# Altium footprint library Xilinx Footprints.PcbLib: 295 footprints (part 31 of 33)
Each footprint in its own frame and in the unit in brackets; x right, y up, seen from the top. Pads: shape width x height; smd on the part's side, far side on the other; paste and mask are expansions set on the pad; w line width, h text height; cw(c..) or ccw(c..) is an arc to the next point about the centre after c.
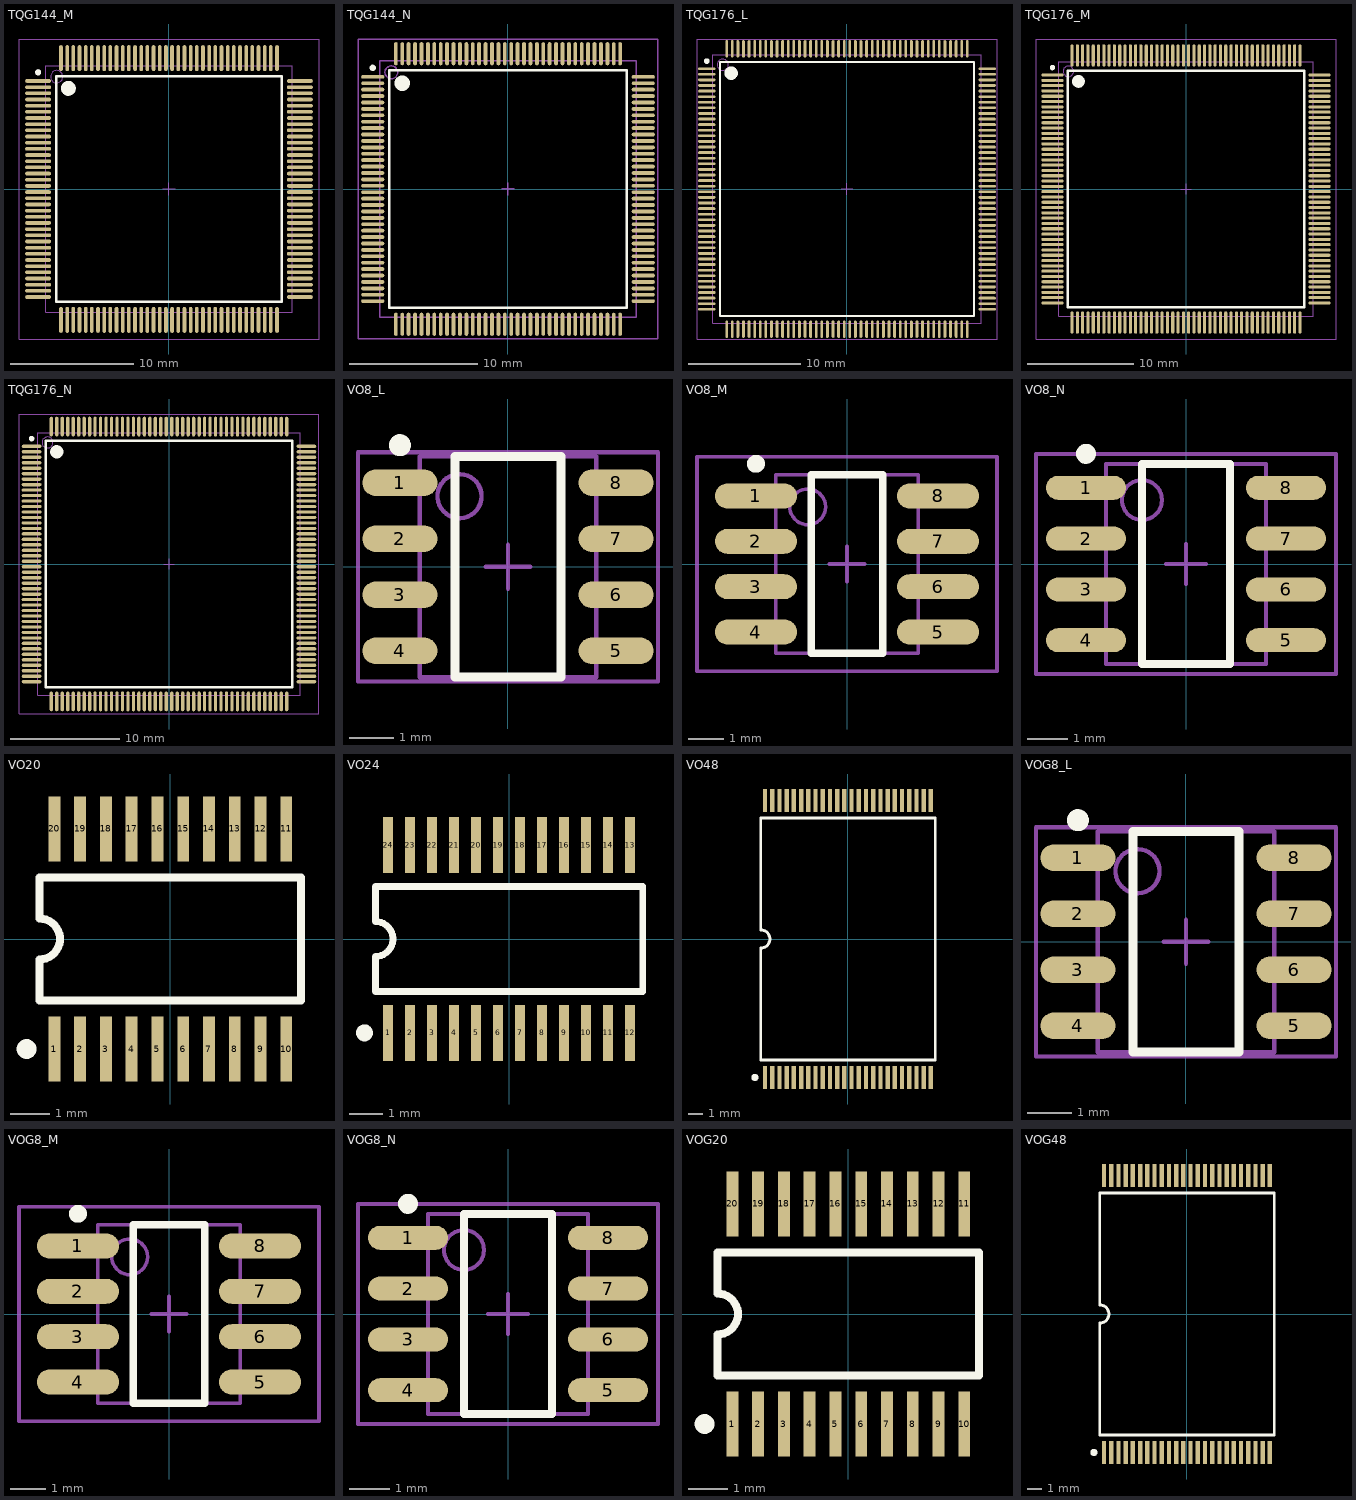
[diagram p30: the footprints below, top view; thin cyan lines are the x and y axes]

## TQG144_M [mm] "144-Pin Thin Quad Flat Pack (TQG144) - Pb-Free, IPC Low Density"
height 1.6
pads (144):
  oval 2.1x0.3 smd: 1(-10.6,8.75) 2(-10.6,8.25) 3(-10.6,7.75) 4(-10.6,7.25) 5(-10.6,6.75) 6(-10.6,6.25) 7(-10.6,5.75) 8(-10.6,5.25) 9(-10.6,4.75) 10(-10.6,4.25) 11(-10.6,3.75) 12(-10.6,3.25) 13(-10.6,2.75) 14(-10.6,2.25) 15(-10.6,1.75) 16(-10.6,1.25) 17(-10.6,0.75) 18(-10.6,0.25) 19(-10.6,-0.25) 20(-10.6,-0.75) 21(-10.6,-1.25) 22(-10.6,-1.75) 23(-10.6,-2.25) 24(-10.6,-2.75) 25(-10.6,-3.25) 26(-10.6,-3.75) 27(-10.6,-4.25) 28(-10.6,-4.75) 29(-10.6,-5.25) 30(-10.6,-5.75) 31(-10.6,-6.25) 32(-10.6,-6.75) 33(-10.6,-7.25) 34(-10.6,-7.75) 35(-10.6,-8.25) 36(-10.6,-8.75) 73(10.6,-8.75) 74(10.6,-8.25) 75(10.6,-7.75) 76(10.6,-7.25) 77(10.6,-6.75) 78(10.6,-6.25) 79(10.6,-5.75) 80(10.6,-5.25) 81(10.6,-4.75) 82(10.6,-4.25) 83(10.6,-3.75) 84(10.6,-3.25) 85(10.6,-2.75) 86(10.6,-2.25) 87(10.6,-1.75) 88(10.6,-1.25) 89(10.6,-0.75) 90(10.6,-0.25) 91(10.6,0.25) 92(10.6,0.75) 93(10.6,1.25) 94(10.6,1.75) 95(10.6,2.25) 96(10.6,2.75) 97(10.6,3.25) 98(10.6,3.75) 99(10.6,4.25) 100(10.6,4.75) 101(10.6,5.25) 102(10.6,5.75) 103(10.6,6.25) 104(10.6,6.75) 105(10.6,7.25) 106(10.6,7.75) 107(10.6,8.25) 108(10.6,8.75)
  oval 0.3x2.1 smd: 37(-8.75,-10.6) 38(-8.25,-10.6) 39(-7.75,-10.6) 40(-7.25,-10.6) 41(-6.75,-10.6) 42(-6.25,-10.6) 43(-5.75,-10.6) 44(-5.25,-10.6) 45(-4.75,-10.6) 46(-4.25,-10.6) 47(-3.75,-10.6) 48(-3.25,-10.6) 49(-2.75,-10.6) 50(-2.25,-10.6) 51(-1.75,-10.6) 52(-1.25,-10.6) 53(-0.75,-10.6) 54(-0.25,-10.6) 55(0.25,-10.6) 56(0.75,-10.6) 57(1.25,-10.6) 58(1.75,-10.6) 59(2.25,-10.6) 60(2.75,-10.6) 61(3.25,-10.6) 62(3.75,-10.6) 63(4.25,-10.6) 64(4.75,-10.6) 65(5.25,-10.6) 66(5.75,-10.6) 67(6.25,-10.6) 68(6.75,-10.6) 69(7.25,-10.6) 70(7.75,-10.6) 71(8.25,-10.6) 72(8.75,-10.6) 109(8.75,10.6) 110(8.25,10.6) 111(7.75,10.6) 112(7.25,10.6) 113(6.75,10.6) 114(6.25,10.6) 115(5.75,10.6) 116(5.25,10.6) 117(4.75,10.6) 118(4.25,10.6) 119(3.75,10.6) 120(3.25,10.6) 121(2.75,10.6) 122(2.25,10.6) 123(1.75,10.6) 124(1.25,10.6) 125(0.75,10.6) 126(0.25,10.6) 127(-0.25,10.6) 128(-0.75,10.6) 129(-1.25,10.6) 130(-1.75,10.6) 131(-2.25,10.6) 132(-2.75,10.6) 133(-3.25,10.6) 134(-3.75,10.6) 135(-4.25,10.6) 136(-4.75,10.6) 137(-5.25,10.6) 138(-5.75,10.6) 139(-6.25,10.6) 140(-6.75,10.6) 141(-7.25,10.6) 142(-7.75,10.6) 143(-8.25,10.6) 144(-8.75,10.6)
Top Overlay:
  circle w0.6: c-8.15,8.15 r0.3
  circle w0.25: c-10.6,9.45 r0.125
  lines w0.2: -9.15,-9.15 9.15,-9.15 9.15,9.15 -9.15,9.15 -9.15,-9.15
Mechanical 13:
  circle w0.1: c-9.1,9.1 r0.5
  lines w0.1: -10,-10 10,-10 10,10 -10,10 -10,-10
Mechanical 15:
  lines w0.1: -0.5,0 0.5,0 ; 0,-0.5 0,0.5 ; -12.15,-12.15 12.15,-12.15 12.15,12.15 -12.15,12.15 -12.15,-12.15
3D body: height 1.6, standoff 0, extent -10,-10 10,10

## TQG144_N [mm] "144-Pin Thin Quad Flat Pack (TQG144) - Pb-Free, IPC Medium Density"
height 1.6
pads (144):
  oval 1.8x0.3 smd: 1(-10.55,8.75) 2(-10.55,8.25) 3(-10.55,7.75) 4(-10.55,7.25) 5(-10.55,6.75) 6(-10.55,6.25) 7(-10.55,5.75) 8(-10.55,5.25) 9(-10.55,4.75) 10(-10.55,4.25) 11(-10.55,3.75) 12(-10.55,3.25) 13(-10.55,2.75) 14(-10.55,2.25) 15(-10.55,1.75) 16(-10.55,1.25) 17(-10.55,0.75) 18(-10.55,0.25) 19(-10.55,-0.25) 20(-10.55,-0.75) 21(-10.55,-1.25) 22(-10.55,-1.75) 23(-10.55,-2.25) 24(-10.55,-2.75) 25(-10.55,-3.25) 26(-10.55,-3.75) 27(-10.55,-4.25) 28(-10.55,-4.75) 29(-10.55,-5.25) 30(-10.55,-5.75) 31(-10.55,-6.25) 32(-10.55,-6.75) 33(-10.55,-7.25) 34(-10.55,-7.75) 35(-10.55,-8.25) 36(-10.55,-8.75) 73(10.55,-8.75) 74(10.55,-8.25) 75(10.55,-7.75) 76(10.55,-7.25) 77(10.55,-6.75) 78(10.55,-6.25) 79(10.55,-5.75) 80(10.55,-5.25) 81(10.55,-4.75) 82(10.55,-4.25) 83(10.55,-3.75) 84(10.55,-3.25) 85(10.55,-2.75) 86(10.55,-2.25) 87(10.55,-1.75) 88(10.55,-1.25) 89(10.55,-0.75) 90(10.55,-0.25) 91(10.55,0.25) 92(10.55,0.75) 93(10.55,1.25) 94(10.55,1.75) 95(10.55,2.25) 96(10.55,2.75) 97(10.55,3.25) 98(10.55,3.75) 99(10.55,4.25) 100(10.55,4.75) 101(10.55,5.25) 102(10.55,5.75) 103(10.55,6.25) 104(10.55,6.75) 105(10.55,7.25) 106(10.55,7.75) 107(10.55,8.25) 108(10.55,8.75)
  oval 0.3x1.8 smd: 37(-8.75,-10.55) 38(-8.25,-10.55) 39(-7.75,-10.55) 40(-7.25,-10.55) 41(-6.75,-10.55) 42(-6.25,-10.55) 43(-5.75,-10.55) 44(-5.25,-10.55) 45(-4.75,-10.55) 46(-4.25,-10.55) 47(-3.75,-10.55) 48(-3.25,-10.55) 49(-2.75,-10.55) 50(-2.25,-10.55) 51(-1.75,-10.55) 52(-1.25,-10.55) 53(-0.75,-10.55) 54(-0.25,-10.55) 55(0.25,-10.55) 56(0.75,-10.55) 57(1.25,-10.55) 58(1.75,-10.55) 59(2.25,-10.55) 60(2.75,-10.55) 61(3.25,-10.55) 62(3.75,-10.55) 63(4.25,-10.55) 64(4.75,-10.55) 65(5.25,-10.55) 66(5.75,-10.55) 67(6.25,-10.55) 68(6.75,-10.55) 69(7.25,-10.55) 70(7.75,-10.55) 71(8.25,-10.55) 72(8.75,-10.55) 109(8.75,10.55) 110(8.25,10.55) 111(7.75,10.55) 112(7.25,10.55) 113(6.75,10.55) 114(6.25,10.55) 115(5.75,10.55) 116(5.25,10.55) 117(4.75,10.55) 118(4.25,10.55) 119(3.75,10.55) 120(3.25,10.55) 121(2.75,10.55) 122(2.25,10.55) 123(1.75,10.55) 124(1.25,10.55) 125(0.75,10.55) 126(0.25,10.55) 127(-0.25,10.55) 128(-0.75,10.55) 129(-1.25,10.55) 130(-1.75,10.55) 131(-2.25,10.55) 132(-2.75,10.55) 133(-3.25,10.55) 134(-3.75,10.55) 135(-4.25,10.55) 136(-4.75,10.55) 137(-5.25,10.55) 138(-5.75,10.55) 139(-6.25,10.55) 140(-6.75,10.55) 141(-7.25,10.55) 142(-7.75,10.55) 143(-8.25,10.55) 144(-8.75,10.55)
Top Overlay:
  circle w0.25: c-10.55,9.45 r0.125
  circle w0.6: c-8.25,8.25 r0.3
  lines w0.2: -9.25,-9.25 -9.25,9.25 9.25,9.25 9.25,-9.25 -9.25,-9.25
Mechanical 13:
  circle w0.1: c-9.1,9.1 r0.5
  lines w0.1: -10,-10 -10,10 10,10 10,-10 -10,-10
Mechanical 15:
  lines w0.1: -0.5,0 0.5,0 ; 0,-0.5 0,0.5 ; -11.7,-11.7 -11.7,11.7 11.7,11.7 11.7,-11.7 -11.7,-11.7
3D body: height 1.6, standoff 0, extent -10,-10 10,10

## TQG176_L [mm] "176-Pin Thin Quad Flat Pack (TQG176) - Pb-Free, IPC High Density"
height 1.6
pads (176):
  oval 1.55x0.25 smd: 1(-12.525,10.75) 2(-12.525,10.25) 3(-12.525,9.75) 4(-12.525,9.25) 5(-12.525,8.75) 6(-12.525,8.25) 7(-12.525,7.75) 8(-12.525,7.25) 9(-12.525,6.75) 10(-12.525,6.25) 11(-12.525,5.75) 12(-12.525,5.25) 13(-12.525,4.75) 14(-12.525,4.25) 15(-12.525,3.75) 16(-12.525,3.25) 17(-12.525,2.75) 18(-12.525,2.25) 19(-12.525,1.75) 20(-12.525,1.25) 21(-12.525,0.75) 22(-12.525,0.25) 23(-12.525,-0.25) 24(-12.525,-0.75) 25(-12.525,-1.25) 26(-12.525,-1.75) 27(-12.525,-2.25) 28(-12.525,-2.75) 29(-12.525,-3.25) 30(-12.525,-3.75) 31(-12.525,-4.25) 32(-12.525,-4.75) 33(-12.525,-5.25) 34(-12.525,-5.75) 35(-12.525,-6.25) 36(-12.525,-6.75) 37(-12.525,-7.25) 38(-12.525,-7.75) 39(-12.525,-8.25) 40(-12.525,-8.75) 41(-12.525,-9.25) 42(-12.525,-9.75) 43(-12.525,-10.25) 44(-12.525,-10.75) 89(12.525,-10.75) 90(12.525,-10.25) 91(12.525,-9.75) 92(12.525,-9.25) 93(12.525,-8.75) 94(12.525,-8.25) 95(12.525,-7.75) 96(12.525,-7.25) 97(12.525,-6.75) 98(12.525,-6.25) 99(12.525,-5.75) 100(12.525,-5.25) 101(12.525,-4.75) 102(12.525,-4.25) 103(12.525,-3.75) 104(12.525,-3.25) 105(12.525,-2.75) 106(12.525,-2.25) 107(12.525,-1.75) 108(12.525,-1.25) 109(12.525,-0.75) 110(12.525,-0.25) 111(12.525,0.25) 112(12.525,0.75) 113(12.525,1.25) 114(12.525,1.75) 115(12.525,2.25) 116(12.525,2.75) 117(12.525,3.25) 118(12.525,3.75) 119(12.525,4.25) 120(12.525,4.75) 121(12.525,5.25) 122(12.525,5.75) 123(12.525,6.25) 124(12.525,6.75) 125(12.525,7.25) 126(12.525,7.75) 127(12.525,8.25) 128(12.525,8.75) 129(12.525,9.25) 130(12.525,9.75) 131(12.525,10.25) 132(12.525,10.75)
  oval 0.25x1.55 smd: 45(-10.75,-12.525) 46(-10.25,-12.525) 47(-9.75,-12.525) 48(-9.25,-12.525) 49(-8.75,-12.525) 50(-8.25,-12.525) 51(-7.75,-12.525) 52(-7.25,-12.525) 53(-6.75,-12.525) 54(-6.25,-12.525) 55(-5.75,-12.525) 56(-5.25,-12.525) 57(-4.75,-12.525) 58(-4.25,-12.525) 59(-3.75,-12.525) 60(-3.25,-12.525) 61(-2.75,-12.525) 62(-2.25,-12.525) 63(-1.75,-12.525) 64(-1.25,-12.525) 65(-0.75,-12.525) 66(-0.25,-12.525) 67(0.25,-12.525) 68(0.75,-12.525) 69(1.25,-12.525) 70(1.75,-12.525) 71(2.25,-12.525) 72(2.75,-12.525) 73(3.25,-12.525) 74(3.75,-12.525) 75(4.25,-12.525) 76(4.75,-12.525) 77(5.25,-12.525) 78(5.75,-12.525) 79(6.25,-12.525) 80(6.75,-12.525) 81(7.25,-12.525) 82(7.75,-12.525) 83(8.25,-12.525) 84(8.75,-12.525) 85(9.25,-12.525) 86(9.75,-12.525) 87(10.25,-12.525) 88(10.75,-12.525) 133(10.75,12.525) 134(10.25,12.525) 135(9.75,12.525) 136(9.25,12.525) 137(8.75,12.525) 138(8.25,12.525) 139(7.75,12.525) 140(7.25,12.525) 141(6.75,12.525) 142(6.25,12.525) 143(5.75,12.525) 144(5.25,12.525) 145(4.75,12.525) 146(4.25,12.525) 147(3.75,12.525) 148(3.25,12.525) 149(2.75,12.525) 150(2.25,12.525) 151(1.75,12.525) 152(1.25,12.525) 153(0.75,12.525) 154(0.25,12.525) 155(-0.25,12.525) 156(-0.75,12.525) 157(-1.25,12.525) 158(-1.75,12.525) 159(-2.25,12.525) 160(-2.75,12.525) 161(-3.25,12.525) 162(-3.75,12.525) 163(-4.25,12.525) 164(-4.75,12.525) 165(-5.25,12.525) 166(-5.75,12.525) 167(-6.25,12.525) 168(-6.75,12.525) 169(-7.25,12.525) 170(-7.75,12.525) 171(-8.25,12.525) 172(-8.75,12.525) 173(-9.25,12.525) 174(-9.75,12.525) 175(-10.25,12.525) 176(-10.75,12.525)
Top Overlay:
  circle w0.6: c-10.35,10.35 r0.3
  circle w0.25: c-12.525,11.425 r0.125
  lines w0.2: -11.35,-11.35 11.35,-11.35 11.35,11.35 -11.35,11.35 -11.35,-11.35
Mechanical 13:
  circle w0.1: c-11.1,11.1 r0.5
  lines w0.1: -12,-12 12,-12 12,12 -12,12 -12,-12
Mechanical 15:
  lines w0.1: -0.5,0 0.5,0 ; 0,-0.5 0,0.5 ; -13.4,-13.4 13.4,-13.4 13.4,13.4 -13.4,13.4 -13.4,-13.4
3D body: height 1.6, standoff 0, extent -12,-12 12,12

## TQG176_M [mm] "176-Pin Thin Quad Flat Pack (TQG176) - Pb-Free, IPC Low Density"
height 1.6
pads (176):
  oval 2.1x0.3 smd: 1(-12.6,10.75) 2(-12.6,10.25) 3(-12.6,9.75) 4(-12.6,9.25) 5(-12.6,8.75) 6(-12.6,8.25) 7(-12.6,7.75) 8(-12.6,7.25) 9(-12.6,6.75) 10(-12.6,6.25) 11(-12.6,5.75) 12(-12.6,5.25) 13(-12.6,4.75) 14(-12.6,4.25) 15(-12.6,3.75) 16(-12.6,3.25) 17(-12.6,2.75) 18(-12.6,2.25) 19(-12.6,1.75) 20(-12.6,1.25) 21(-12.6,0.75) 22(-12.6,0.25) 23(-12.6,-0.25) 24(-12.6,-0.75) 25(-12.6,-1.25) 26(-12.6,-1.75) 27(-12.6,-2.25) 28(-12.6,-2.75) 29(-12.6,-3.25) 30(-12.6,-3.75) 31(-12.6,-4.25) 32(-12.6,-4.75) 33(-12.6,-5.25) 34(-12.6,-5.75) 35(-12.6,-6.25) 36(-12.6,-6.75) 37(-12.6,-7.25) 38(-12.6,-7.75) 39(-12.6,-8.25) 40(-12.6,-8.75) 41(-12.6,-9.25) 42(-12.6,-9.75) 43(-12.6,-10.25) 44(-12.6,-10.75) 89(12.6,-10.75) 90(12.6,-10.25) 91(12.6,-9.75) 92(12.6,-9.25) 93(12.6,-8.75) 94(12.6,-8.25) 95(12.6,-7.75) 96(12.6,-7.25) 97(12.6,-6.75) 98(12.6,-6.25) 99(12.6,-5.75) 100(12.6,-5.25) 101(12.6,-4.75) 102(12.6,-4.25) 103(12.6,-3.75) 104(12.6,-3.25) 105(12.6,-2.75) 106(12.6,-2.25) 107(12.6,-1.75) 108(12.6,-1.25) 109(12.6,-0.75) 110(12.6,-0.25) 111(12.6,0.25) 112(12.6,0.75) 113(12.6,1.25) 114(12.6,1.75) 115(12.6,2.25) 116(12.6,2.75) 117(12.6,3.25) 118(12.6,3.75) 119(12.6,4.25) 120(12.6,4.75) 121(12.6,5.25) 122(12.6,5.75) 123(12.6,6.25) 124(12.6,6.75) 125(12.6,7.25) 126(12.6,7.75) 127(12.6,8.25) 128(12.6,8.75) 129(12.6,9.25) 130(12.6,9.75) 131(12.6,10.25) 132(12.6,10.75)
  oval 0.3x2.1 smd: 45(-10.75,-12.6) 46(-10.25,-12.6) 47(-9.75,-12.6) 48(-9.25,-12.6) 49(-8.75,-12.6) 50(-8.25,-12.6) 51(-7.75,-12.6) 52(-7.25,-12.6) 53(-6.75,-12.6) 54(-6.25,-12.6) 55(-5.75,-12.6) 56(-5.25,-12.6) 57(-4.75,-12.6) 58(-4.25,-12.6) 59(-3.75,-12.6) 60(-3.25,-12.6) 61(-2.75,-12.6) 62(-2.25,-12.6) 63(-1.75,-12.6) 64(-1.25,-12.6) 65(-0.75,-12.6) 66(-0.25,-12.6) 67(0.25,-12.6) 68(0.75,-12.6) 69(1.25,-12.6) 70(1.75,-12.6) 71(2.25,-12.6) 72(2.75,-12.6) 73(3.25,-12.6) 74(3.75,-12.6) 75(4.25,-12.6) 76(4.75,-12.6) 77(5.25,-12.6) 78(5.75,-12.6) 79(6.25,-12.6) 80(6.75,-12.6) 81(7.25,-12.6) 82(7.75,-12.6) 83(8.25,-12.6) 84(8.75,-12.6) 85(9.25,-12.6) 86(9.75,-12.6) 87(10.25,-12.6) 88(10.75,-12.6) 133(10.75,12.6) 134(10.25,12.6) 135(9.75,12.6) 136(9.25,12.6) 137(8.75,12.6) 138(8.25,12.6) 139(7.75,12.6) 140(7.25,12.6) 141(6.75,12.6) 142(6.25,12.6) 143(5.75,12.6) 144(5.25,12.6) 145(4.75,12.6) 146(4.25,12.6) 147(3.75,12.6) 148(3.25,12.6) 149(2.75,12.6) 150(2.25,12.6) 151(1.75,12.6) 152(1.25,12.6) 153(0.75,12.6) 154(0.25,12.6) 155(-0.25,12.6) 156(-0.75,12.6) 157(-1.25,12.6) 158(-1.75,12.6) 159(-2.25,12.6) 160(-2.75,12.6) 161(-3.25,12.6) 162(-3.75,12.6) 163(-4.25,12.6) 164(-4.75,12.6) 165(-5.25,12.6) 166(-5.75,12.6) 167(-6.25,12.6) 168(-6.75,12.6) 169(-7.25,12.6) 170(-7.75,12.6) 171(-8.25,12.6) 172(-8.75,12.6) 173(-9.25,12.6) 174(-9.75,12.6) 175(-10.25,12.6) 176(-10.75,12.6)
Top Overlay:
  circle w0.6: c-10.15,10.15 r0.3
  circle w0.25: c-12.6,11.45 r0.125
  lines w0.2: -11.15,-11.15 11.15,-11.15 11.15,11.15 -11.15,11.15 -11.15,-11.15
Mechanical 13:
  circle w0.1: c-11.1,11.1 r0.5
  lines w0.1: -12,-12 12,-12 12,12 -12,12 -12,-12
Mechanical 15:
  lines w0.1: -0.5,0 0.5,0 ; 0,-0.5 0,0.5 ; -14.15,-14.15 14.15,-14.15 14.15,14.15 -14.15,14.15 -14.15,-14.15
3D body: height 1.6, standoff 0, extent -12,-12 12,12

## TQG176_N [mm] "176-Pin Thin Quad Flat Pack (TQG176) - Pb-Free, IPC Medium Density"
height 1.6
pads (176):
  oval 1.8x0.3 smd: 1(-12.55,10.75) 2(-12.55,10.25) 3(-12.55,9.75) 4(-12.55,9.25) 5(-12.55,8.75) 6(-12.55,8.25) 7(-12.55,7.75) 8(-12.55,7.25) 9(-12.55,6.75) 10(-12.55,6.25) 11(-12.55,5.75) 12(-12.55,5.25) 13(-12.55,4.75) 14(-12.55,4.25) 15(-12.55,3.75) 16(-12.55,3.25) 17(-12.55,2.75) 18(-12.55,2.25) 19(-12.55,1.75) 20(-12.55,1.25) 21(-12.55,0.75) 22(-12.55,0.25) 23(-12.55,-0.25) 24(-12.55,-0.75) 25(-12.55,-1.25) 26(-12.55,-1.75) 27(-12.55,-2.25) 28(-12.55,-2.75) 29(-12.55,-3.25) 30(-12.55,-3.75) 31(-12.55,-4.25) 32(-12.55,-4.75) 33(-12.55,-5.25) 34(-12.55,-5.75) 35(-12.55,-6.25) 36(-12.55,-6.75) 37(-12.55,-7.25) 38(-12.55,-7.75) 39(-12.55,-8.25) 40(-12.55,-8.75) 41(-12.55,-9.25) 42(-12.55,-9.75) 43(-12.55,-10.25) 44(-12.55,-10.75) 89(12.55,-10.75) 90(12.55,-10.25) 91(12.55,-9.75) 92(12.55,-9.25) 93(12.55,-8.75) 94(12.55,-8.25) 95(12.55,-7.75) 96(12.55,-7.25) 97(12.55,-6.75) 98(12.55,-6.25) 99(12.55,-5.75) 100(12.55,-5.25) 101(12.55,-4.75) 102(12.55,-4.25) 103(12.55,-3.75) 104(12.55,-3.25) 105(12.55,-2.75) 106(12.55,-2.25) 107(12.55,-1.75) 108(12.55,-1.25) 109(12.55,-0.75) 110(12.55,-0.25) 111(12.55,0.25) 112(12.55,0.75) 113(12.55,1.25) 114(12.55,1.75) 115(12.55,2.25) 116(12.55,2.75) 117(12.55,3.25) 118(12.55,3.75) 119(12.55,4.25) 120(12.55,4.75) 121(12.55,5.25) 122(12.55,5.75) 123(12.55,6.25) 124(12.55,6.75) 125(12.55,7.25) 126(12.55,7.75) 127(12.55,8.25) 128(12.55,8.75) 129(12.55,9.25) 130(12.55,9.75) 131(12.55,10.25) 132(12.55,10.75)
  oval 0.3x1.8 smd: 45(-10.75,-12.55) 46(-10.25,-12.55) 47(-9.75,-12.55) 48(-9.25,-12.55) 49(-8.75,-12.55) 50(-8.25,-12.55) 51(-7.75,-12.55) 52(-7.25,-12.55) 53(-6.75,-12.55) 54(-6.25,-12.55) 55(-5.75,-12.55) 56(-5.25,-12.55) 57(-4.75,-12.55) 58(-4.25,-12.55) 59(-3.75,-12.55) 60(-3.25,-12.55) 61(-2.75,-12.55) 62(-2.25,-12.55) 63(-1.75,-12.55) 64(-1.25,-12.55) 65(-0.75,-12.55) 66(-0.25,-12.55) 67(0.25,-12.55) 68(0.75,-12.55) 69(1.25,-12.55) 70(1.75,-12.55) 71(2.25,-12.55) 72(2.75,-12.55) 73(3.25,-12.55) 74(3.75,-12.55) 75(4.25,-12.55) 76(4.75,-12.55) 77(5.25,-12.55) 78(5.75,-12.55) 79(6.25,-12.55) 80(6.75,-12.55) 81(7.25,-12.55) 82(7.75,-12.55) 83(8.25,-12.55) 84(8.75,-12.55) 85(9.25,-12.55) 86(9.75,-12.55) 87(10.25,-12.55) 88(10.75,-12.55) 133(10.75,12.55) 134(10.25,12.55) 135(9.75,12.55) 136(9.25,12.55) 137(8.75,12.55) 138(8.25,12.55) 139(7.75,12.55) 140(7.25,12.55) 141(6.75,12.55) 142(6.25,12.55) 143(5.75,12.55) 144(5.25,12.55) 145(4.75,12.55) 146(4.25,12.55) 147(3.75,12.55) 148(3.25,12.55) 149(2.75,12.55) 150(2.25,12.55) 151(1.75,12.55) 152(1.25,12.55) 153(0.75,12.55) 154(0.25,12.55) 155(-0.25,12.55) 156(-0.75,12.55) 157(-1.25,12.55) 158(-1.75,12.55) 159(-2.25,12.55) 160(-2.75,12.55) 161(-3.25,12.55) 162(-3.75,12.55) 163(-4.25,12.55) 164(-4.75,12.55) 165(-5.25,12.55) 166(-5.75,12.55) 167(-6.25,12.55) 168(-6.75,12.55) 169(-7.25,12.55) 170(-7.75,12.55) 171(-8.25,12.55) 172(-8.75,12.55) 173(-9.25,12.55) 174(-9.75,12.55) 175(-10.25,12.55) 176(-10.75,12.55)
Top Overlay:
  circle w0.25: c-12.55,11.45 r0.125
  circle w0.6: c-10.25,10.25 r0.3
  lines w0.2: -11.25,-11.25 -11.25,11.25 11.25,11.25 11.25,-11.25 -11.25,-11.25
Mechanical 13:
  circle w0.1: c-11.1,11.1 r0.5
  lines w0.1: -12,-12 -12,12 12,12 12,-12 -12,-12
Mechanical 15:
  lines w0.1: -0.5,0 0.5,0 ; 0,-0.5 0,0.5 ; -13.7,-13.7 -13.7,13.7 13.7,13.7 13.7,-13.7 -13.7,-13.7
3D body: height 1.6, standoff 0, extent -12,-12 12,12

## VO8_L [mm] "8-Pin Thin Small Outline Package (VO8), IPC High Density"
height 1.2
pads (8):
  oval 1.7x0.6 smd: 1(-2.45,1.905) 2(-2.45,0.635) 3(-2.45,-0.635) 4(-2.45,-1.905) 5(2.45,-1.905) 6(2.45,-0.635) 7(2.45,0.635) 8(2.45,1.905)
Top Overlay:
  circle w0.25: c-2.45,2.755 r0.125
  lines w0.2: -1.2,-2.5 -1.2,2.5 1.2,2.5 1.2,-2.5 -1.2,-2.5
Mechanical 13:
  circle w0.1: c-1.1,1.6 r0.5
  lines w0.1: -2,-2.5 -2,2.5 2,2.5 2,-2.5 -2,-2.5
Mechanical 15:
  lines w0.1: -0.5,0 0.5,0 ; 0,-0.5 0,0.5 ; -3.4,-2.6 -3.4,2.6 3.4,2.6 3.4,-2.6 -3.4,-2.6
3D body: height 1.2, standoff 0, extent -2,-2.5 2,2.5

## VO8_M [mm] "8-Pin Thin Small Outline Package (VO8), IPC Low Density"
height 1.2
pads (8):
  oval 2.3x0.7 smd: 1(-2.55,1.905) 2(-2.55,0.635) 3(-2.55,-0.635) 4(-2.55,-1.905) 5(2.55,-1.905) 6(2.55,-0.635) 7(2.55,0.635) 8(2.55,1.905)
Top Overlay:
  circle w0.25: c-2.55,2.805 r0.125
  lines w0.2: -1,-2.5 -1,2.5 1,2.5 1,-2.5 -1,-2.5
Mechanical 13:
  circle w0.1: c-1.1,1.6 r0.5
  lines w0.1: -2,-2.5 -2,2.5 2,2.5 2,-2.5 -2,-2.5
Mechanical 15:
  lines w0.1: -0.5,0 0.5,0 ; 0,-0.5 0,0.5 ; -4.2,-3 -4.2,3 4.2,3 4.2,-3 -4.2,-3
3D body: height 1.2, standoff 0, extent -2,-2.5 2,2.5

## VO8_N [mm] "8-Pin Thin Small Outline Package (VO8), IPC Medium Density"
height 1.2
pads (8):
  oval 2x0.6 smd: 1(-2.5,1.905) 2(-2.5,0.635) 3(-2.5,-0.635) 4(-2.5,-1.905) 5(2.5,-1.905) 6(2.5,-0.635) 7(2.5,0.635) 8(2.5,1.905)
Top Overlay:
  circle w0.25: c-2.5,2.755 r0.125
  lines w0.2: -1.1,-2.5 -1.1,2.5 1.1,2.5 1.1,-2.5 -1.1,-2.5
Mechanical 13:
  circle w0.1: c-1.1,1.6 r0.5
  lines w0.1: -2,-2.5 -2,2.5 2,2.5 2,-2.5 -2,-2.5
Mechanical 15:
  lines w0.1: -0.5,0 0.5,0 ; 0,-0.5 0,0.5 ; -3.75,-2.75 -3.75,2.75 3.75,2.75 3.75,-2.75 -3.75,-2.75
3D body: height 1.2, standoff 0, extent -2,-2.5 2,2.5

## VO20 [mm] "20-Pin Thin Shrink Small Outline Package (VO20)"
height 1.2
pads (20):
  rect 0.3x1.65 smd: 1(-2.925,-2.775) 2(-2.275,-2.775) 3(-1.625,-2.775) 4(-0.975,-2.775) 5(-0.325,-2.775) 6(0.325,-2.775) 7(0.975,-2.775) 8(1.625,-2.775) 9(2.275,-2.775) 10(2.925,-2.775) 11(2.925,2.775) 12(2.275,2.775) 13(1.625,2.775) 14(0.975,2.775) 15(0.325,2.775) 16(-0.325,2.775) 17(-0.975,2.775) 18(-1.625,2.775) 19(-2.275,2.775) 20(-2.925,2.775)
Top Overlay:
  circle w0.25: c-3.625,-2.775 r0.125
  lines w0.2: -3.3,-1.55 3.3,-1.55 3.3,1.55 -3.3,1.55 -3.3,0.517 cw(c-3.3,0) -3.3,-0.517 -3.3,-1.55

## VO24 [mm] "24-Pin Thin Small Outline Package (VO24)"
height 1.2
pads (24):
  rect 0.3x1.65 smd: 1(-3.575,-2.775) 2(-2.925,-2.775) 3(-2.275,-2.775) 4(-1.625,-2.775) 5(-0.975,-2.775) 6(-0.325,-2.775) 7(0.325,-2.775) 8(0.975,-2.775) 9(1.625,-2.775) 10(2.275,-2.775) 11(2.925,-2.775) 12(3.575,-2.775) 13(3.575,2.775) 14(2.925,2.775) 15(2.275,2.775) 16(1.625,2.775) 17(0.975,2.775) 18(0.325,2.775) 19(-0.325,2.775) 20(-0.975,2.775) 21(-1.625,2.775) 22(-2.275,2.775) 23(-2.925,2.775) 24(-3.575,2.775)
Top Overlay:
  circle w0.25: c-4.275,-2.775 r0.125
  lines w0.2: -3.95,-1.55 -3.95,-0.517 ccw(c-3.95,0) -3.95,0.517 -3.95,1.55 3.95,1.55 3.95,-1.55 -3.95,-1.55

## VO48 [mm] "48-Pin Thin Small Outline Package 0.5 mm Pitch (VO48)"
height 1.2
pads (48):
  rect 0.3x1.6 smd: 1(-5.75,-9.6) 2(-5.25,-9.6) 3(-4.75,-9.6) 4(-4.25,-9.6) 5(-3.75,-9.6) 6(-3.25,-9.6) 7(-2.75,-9.6) 8(-2.25,-9.6) 9(-1.75,-9.6) 10(-1.25,-9.6) 11(-0.75,-9.6) 12(-0.25,-9.6) 13(0.25,-9.6) 14(0.75,-9.6) 15(1.25,-9.6) 16(1.75,-9.6) 17(2.25,-9.6) 18(2.75,-9.6) 19(3.25,-9.6) 20(3.75,-9.6) 21(4.25,-9.6) 22(4.75,-9.6) 23(5.25,-9.6) 24(5.75,-9.6) 25(5.75,9.6) 26(5.25,9.6) 27(4.75,9.6) 28(4.25,9.6) 29(3.75,9.6) 30(3.25,9.6) 31(2.75,9.6) 32(2.25,9.6) 33(1.75,9.6) 34(1.25,9.6) 35(0.75,9.6) 36(0.25,9.6) 37(-0.25,9.6) 38(-0.75,9.6) 39(-1.25,9.6) 40(-1.75,9.6) 41(-2.25,9.6) 42(-2.75,9.6) 43(-3.25,9.6) 44(-3.75,9.6) 45(-4.25,9.6) 46(-4.75,9.6) 47(-5.25,9.6) 48(-5.75,9.6)
Top Overlay:
  circle w0.25: c-6.45,-9.6 r0.125
  lines w0.2: -6.05,-8.4 -6.05,-0.635 ccw(c-6.05,0) -6.05,0.635 -6.05,8.4 6.05,8.4 6.05,-8.4 -6.05,-8.4

## VOG8_L [mm] "8-Pin Thin Small Outline Package (VOG8) - Pb-Free, IPC High Density"
height 1.2
pads (8):
  oval 1.7x0.6 smd: 1(-2.45,1.905) 2(-2.45,0.635) 3(-2.45,-0.635) 4(-2.45,-1.905) 5(2.45,-1.905) 6(2.45,-0.635) 7(2.45,0.635) 8(2.45,1.905)
Top Overlay:
  circle w0.25: c-2.45,2.755 r0.125
  lines w0.2: -1.2,-2.5 -1.2,2.5 1.2,2.5 1.2,-2.5 -1.2,-2.5
Mechanical 13:
  circle w0.1: c-1.1,1.6 r0.5
  lines w0.1: -2,-2.5 -2,2.5 2,2.5 2,-2.5 -2,-2.5
Mechanical 15:
  lines w0.1: -0.5,0 0.5,0 ; 0,-0.5 0,0.5 ; -3.4,-2.6 -3.4,2.6 3.4,2.6 3.4,-2.6 -3.4,-2.6
3D body: height 1.2, standoff 0, extent -2,-2.5 2,2.5

## VOG8_M [mm] "8-Pin Thin Small Outline Package (VOG8) - Pb-Free, IPC Low Density"
height 1.2
pads (8):
  oval 2.3x0.7 smd: 1(-2.55,1.905) 2(-2.55,0.635) 3(-2.55,-0.635) 4(-2.55,-1.905) 5(2.55,-1.905) 6(2.55,-0.635) 7(2.55,0.635) 8(2.55,1.905)
Top Overlay:
  circle w0.25: c-2.55,2.805 r0.125
  lines w0.2: -1,-2.5 1,-2.5 1,2.5 -1,2.5 -1,-2.5
Mechanical 13:
  circle w0.1: c-1.1,1.6 r0.5
  lines w0.1: -2,-2.5 2,-2.5 2,2.5 -2,2.5 -2,-2.5
Mechanical 15:
  lines w0.1: -0.5,0 0.5,0 ; 0,-0.5 0,0.5 ; -4.2,-3 4.2,-3 4.2,3 -4.2,3 -4.2,-3
3D body: height 1.2, standoff 0, extent -2,-2.5 2,2.5

## VOG8_N [mm] "8-Pin Thin Small Outline Package (VOG8) - Pb-Free, IPC Medium Density"
height 1.2
pads (8):
  oval 2x0.6 smd: 1(-2.5,1.905) 2(-2.5,0.635) 3(-2.5,-0.635) 4(-2.5,-1.905) 5(2.5,-1.905) 6(2.5,-0.635) 7(2.5,0.635) 8(2.5,1.905)
Top Overlay:
  circle w0.25: c-2.5,2.755 r0.125
  lines w0.2: -1.1,-2.5 1.1,-2.5 1.1,2.5 -1.1,2.5 -1.1,-2.5
Mechanical 13:
  circle w0.1: c-1.1,1.6 r0.5
  lines w0.1: -2,-2.5 2,-2.5 2,2.5 -2,2.5 -2,-2.5
Mechanical 15:
  lines w0.1: -0.5,0 0.5,0 ; 0,-0.5 0,0.5 ; -3.75,-2.75 3.75,-2.75 3.75,2.75 -3.75,2.75 -3.75,-2.75
3D body: height 1.2, standoff 0, extent -2,-2.5 2,2.5

## VOG20 [mm] "20-Pin Thin Shrink Small Outline Package (VOG20) - Pb-Free"
height 1.2
pads (20):
  rect 0.3x1.65 smd: 1(-2.925,-2.775) 2(-2.275,-2.775) 3(-1.625,-2.775) 4(-0.975,-2.775) 5(-0.325,-2.775) 6(0.325,-2.775) 7(0.975,-2.775) 8(1.625,-2.775) 9(2.275,-2.775) 10(2.925,-2.775) 11(2.925,2.775) 12(2.275,2.775) 13(1.625,2.775) 14(0.975,2.775) 15(0.325,2.775) 16(-0.325,2.775) 17(-0.975,2.775) 18(-1.625,2.775) 19(-2.275,2.775) 20(-2.925,2.775)
Top Overlay:
  circle w0.25: c-3.625,-2.775 r0.125
  lines w0.2: -3.3,-1.55 3.3,-1.55 3.3,1.55 -3.3,1.55 -3.3,0.517 cw(c-3.3,0) -3.3,-0.517 -3.3,-1.55

## VOG48 [mm] "48-Pin Thin Small Outline Package 0.5 mm Pitch (VOG48) - Pb-Free"
height 1.2
pads (48):
  rect 0.3x1.6 smd: 1(-5.75,-9.6) 2(-5.25,-9.6) 3(-4.75,-9.6) 4(-4.25,-9.6) 5(-3.75,-9.6) 6(-3.25,-9.6) 7(-2.75,-9.6) 8(-2.25,-9.6) 9(-1.75,-9.6) 10(-1.25,-9.6) 11(-0.75,-9.6) 12(-0.25,-9.6) 13(0.25,-9.6) 14(0.75,-9.6) 15(1.25,-9.6) 16(1.75,-9.6) 17(2.25,-9.6) 18(2.75,-9.6) 19(3.25,-9.6) 20(3.75,-9.6) 21(4.25,-9.6) 22(4.75,-9.6) 23(5.25,-9.6) 24(5.75,-9.6) 25(5.75,9.6) 26(5.25,9.6) 27(4.75,9.6) 28(4.25,9.6) 29(3.75,9.6) 30(3.25,9.6) 31(2.75,9.6) 32(2.25,9.6) 33(1.75,9.6) 34(1.25,9.6) 35(0.75,9.6) 36(0.25,9.6) 37(-0.25,9.6) 38(-0.75,9.6) 39(-1.25,9.6) 40(-1.75,9.6) 41(-2.25,9.6) 42(-2.75,9.6) 43(-3.25,9.6) 44(-3.75,9.6) 45(-4.25,9.6) 46(-4.75,9.6) 47(-5.25,9.6) 48(-5.75,9.6)
Top Overlay:
  circle w0.25: c-6.45,-9.6 r0.125
  lines w0.2: -6.05,-8.4 -6.05,-0.635 ccw(c-6.05,0) -6.05,0.635 -6.05,8.4 6.05,8.4 6.05,-8.4 -6.05,-8.4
